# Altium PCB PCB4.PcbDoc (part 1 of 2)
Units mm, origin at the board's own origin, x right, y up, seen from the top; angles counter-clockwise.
Board outline 70 x 70 mm, 2 copper layers (Top Layer, Bottom Layer); 41 components, 63 nets, 218 pads, 36 vias.
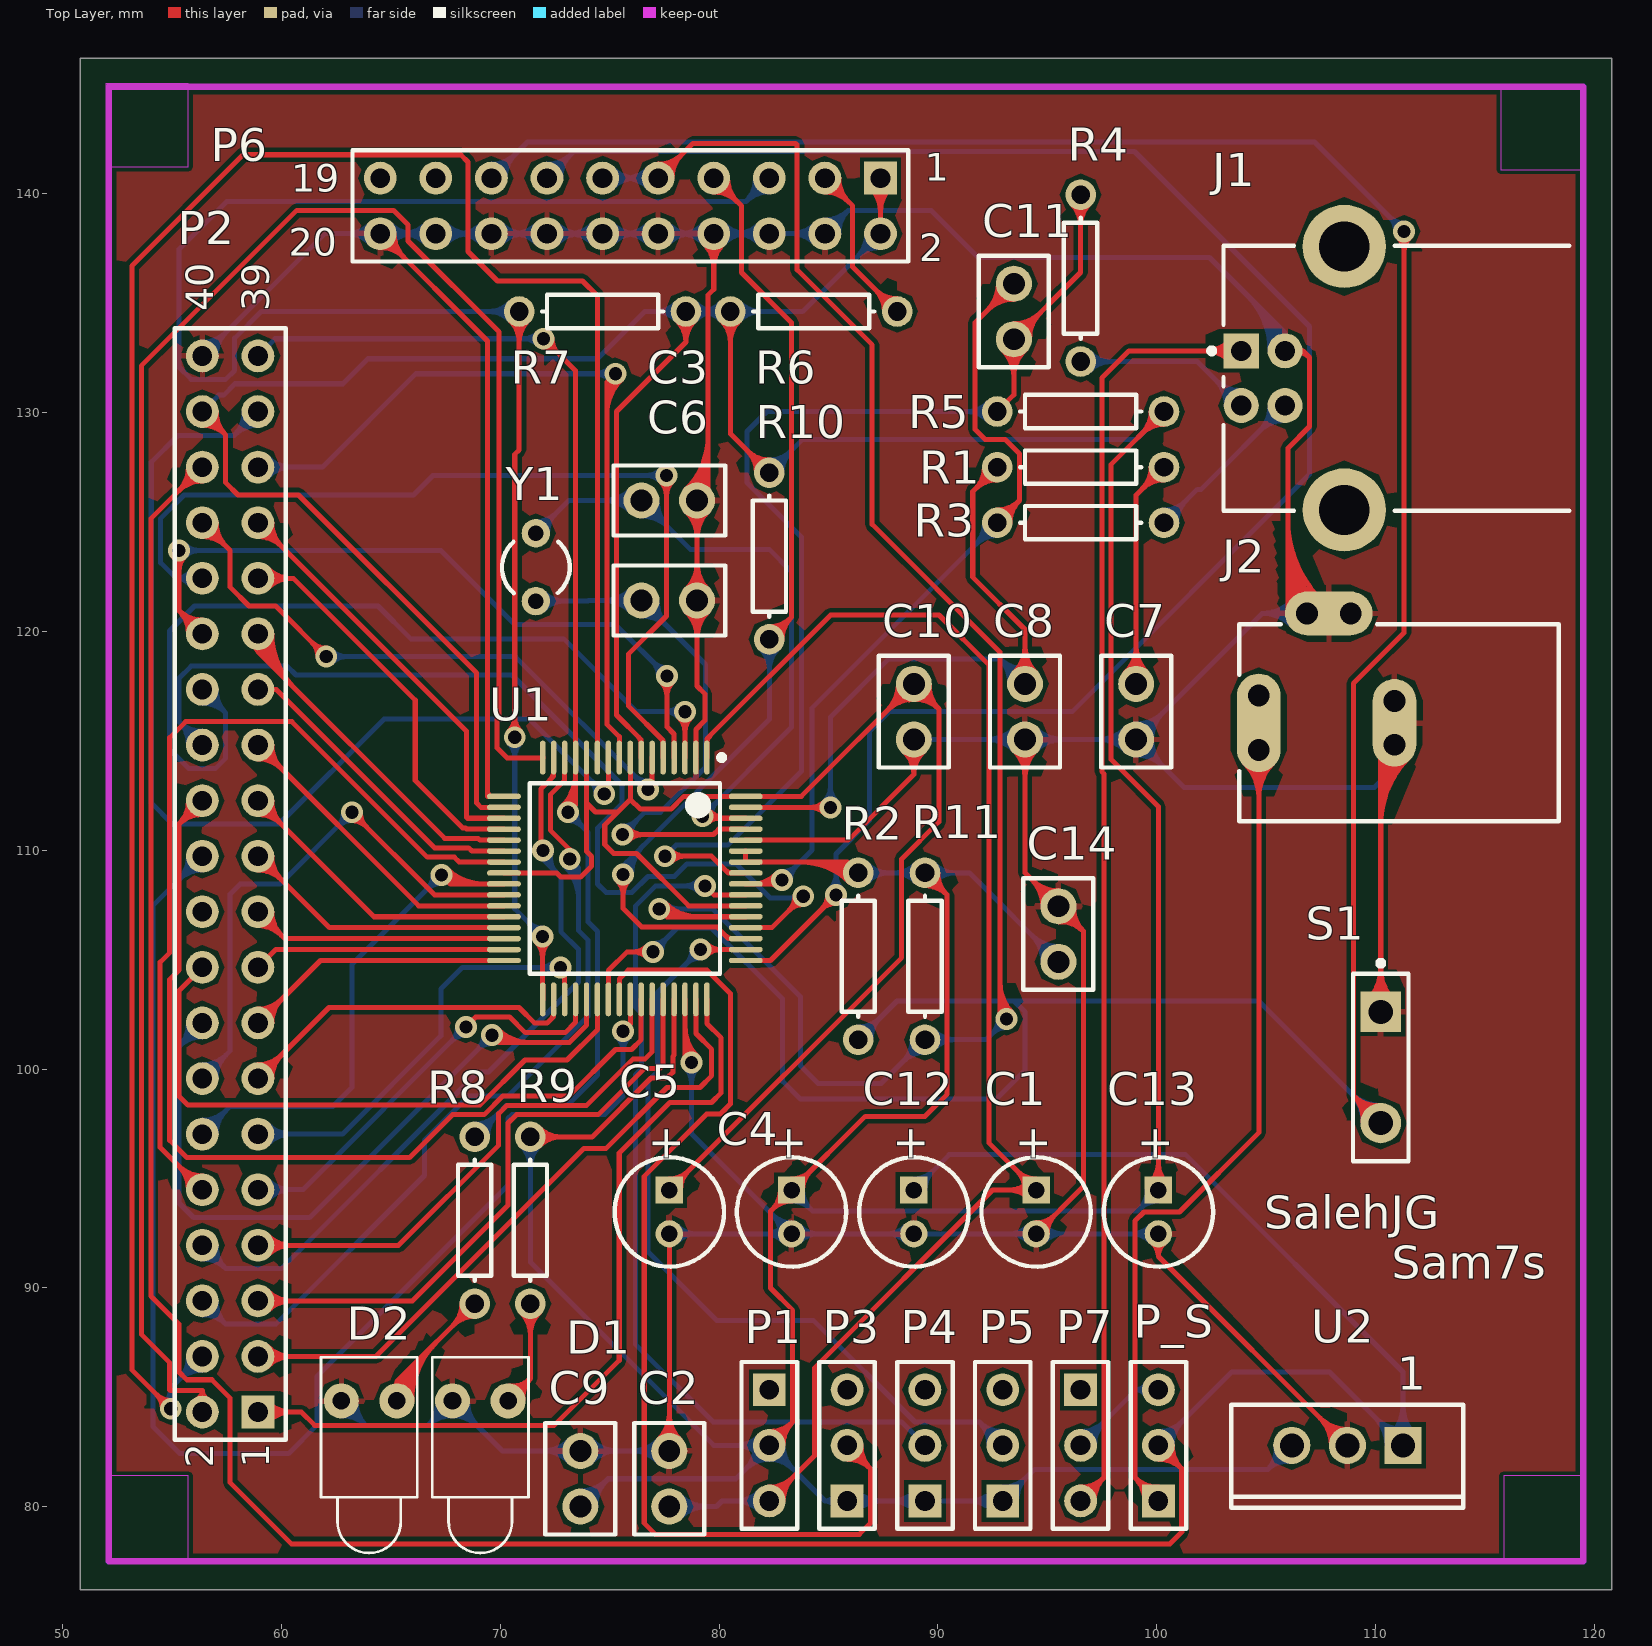
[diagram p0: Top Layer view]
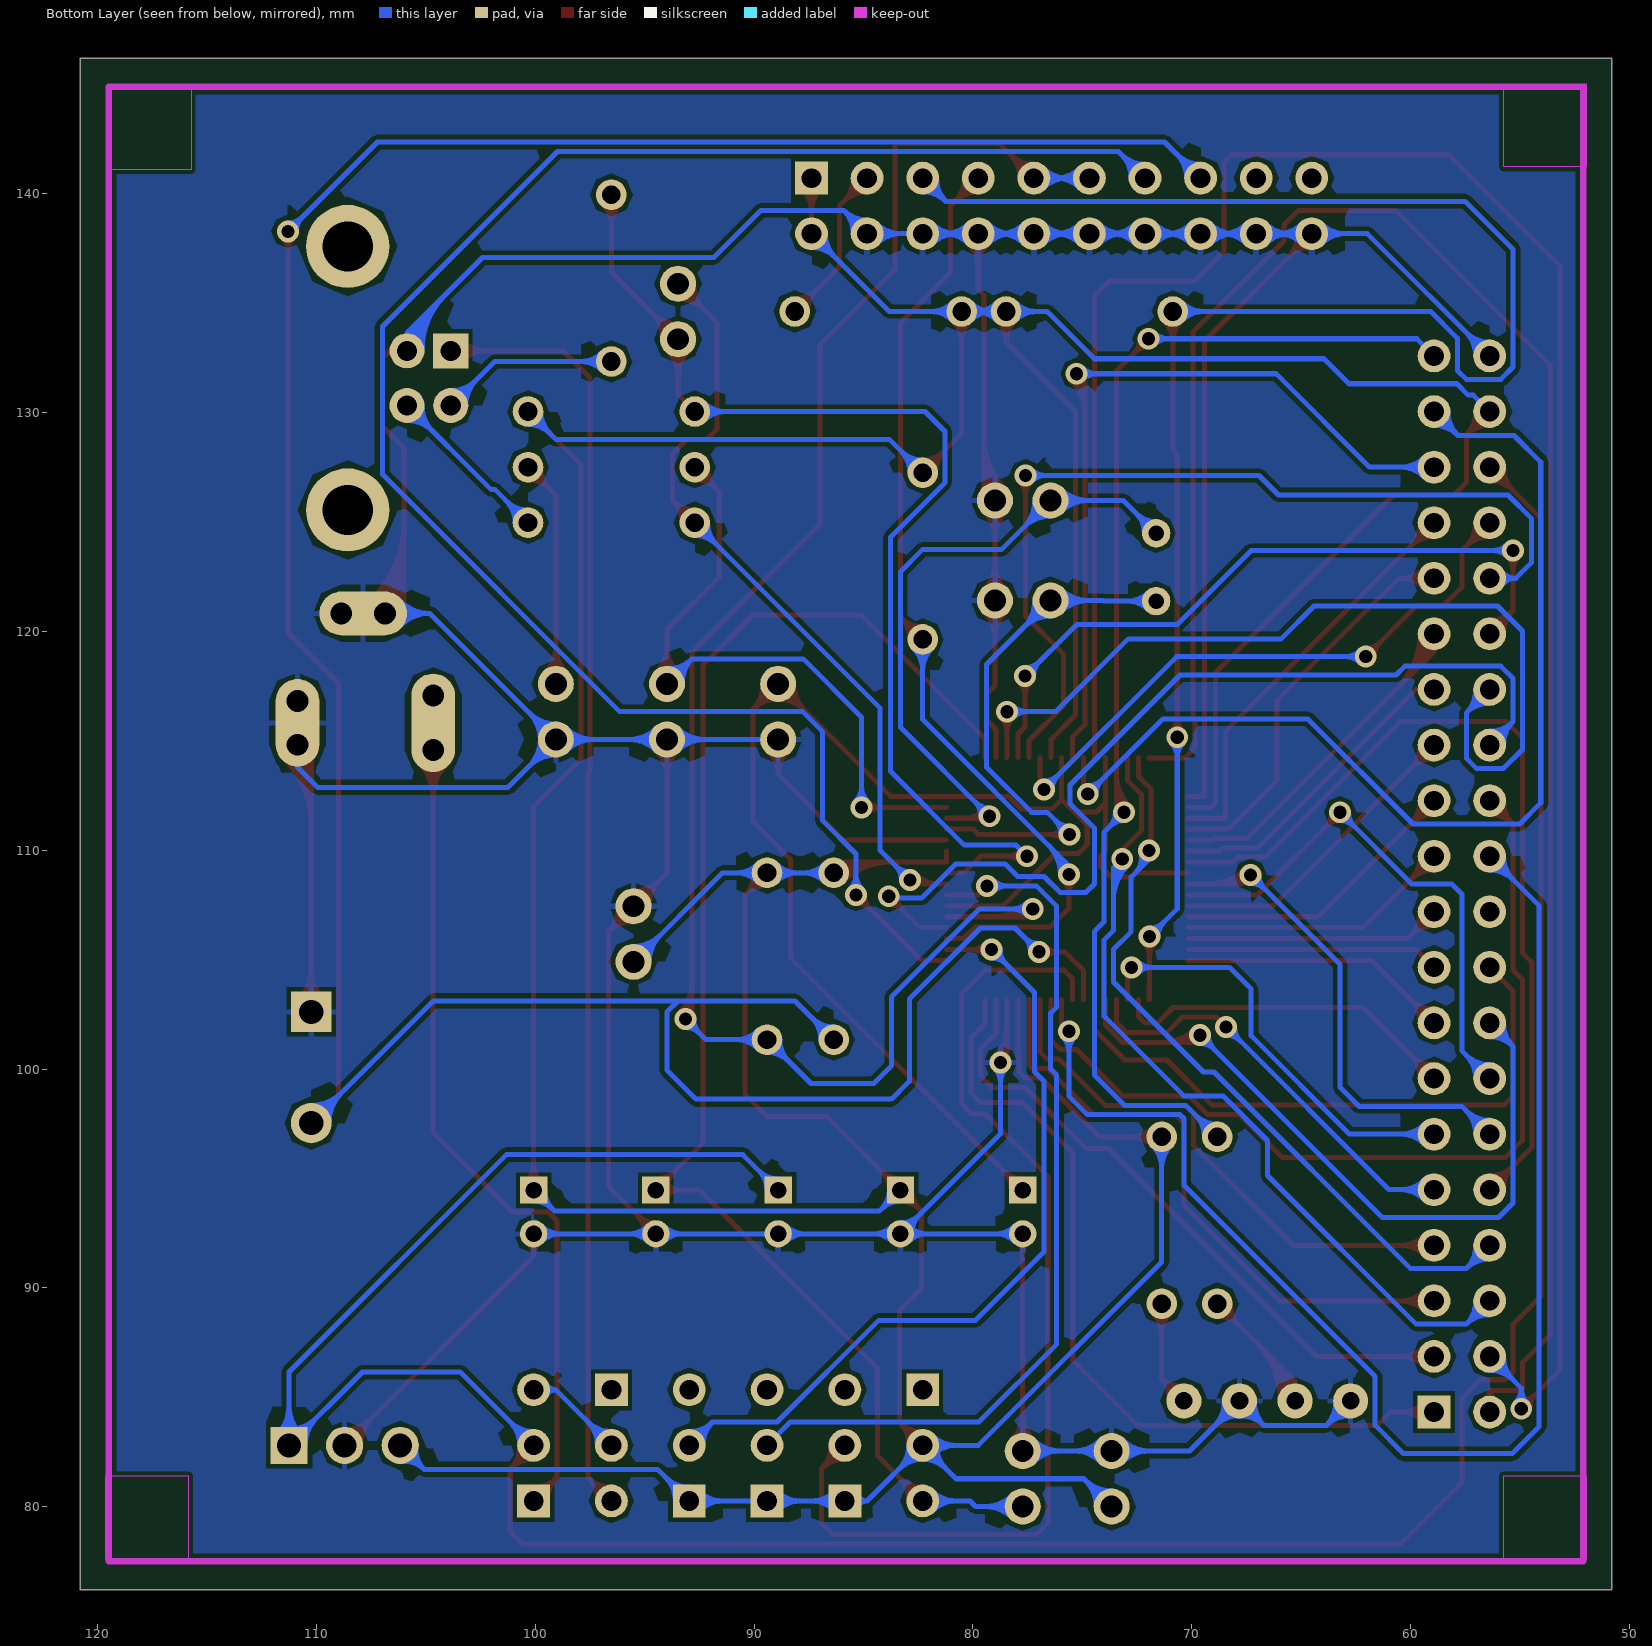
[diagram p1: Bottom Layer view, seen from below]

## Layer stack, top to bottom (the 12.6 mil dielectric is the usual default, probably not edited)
Top Layer: signal copper 0.0356
Dielectric: dielectric 0.32, FR-4, Dk 4.8
Bottom Layer: signal copper 0.0356

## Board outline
50.8,76.2 120.8,76.2 120.8,146.2 50.8,146.2

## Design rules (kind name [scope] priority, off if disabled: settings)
Clearance [All] p1: gap=0.2
PolygonConnect [All] p1: connectstyle=Relief reliefconductorwidth=0.254 reliefentries=4 polygonreliefangle="90 Angle"
RoutingVias [All] p1: holewidth=0.6 width=1 viastyle="Through Hole" minholewidth=0.711 minwidth=1.27 maxholewidth=0.711 maxwidth=1.27
SMDNeckDown [All] p1: percent=100.000
SilkscreenOverComponentPads [All] p1: minsilkscreentomaskgap=0.254
SolderMaskExpansion [All] p1: expansion=0.102
TestPointUsage [All] p1: valid=0 allowmultiple=FALSE
Testpoint [All] p1: side=15 testpointundercomponent=TRUE minsize=1.016 maxsize=2.54 preferedsize=1.524 minholesize=0 maxholesize=1.016 preferedholesize=0.813 testpointgrid=0.025 style=1023 order=0123456789
Width [All] p1: maxlimit=0.3 minlimit=0.2 preferedwidth=0.23
23 further rules are at their usual default settings.

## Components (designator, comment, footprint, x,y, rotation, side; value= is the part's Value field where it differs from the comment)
C1 "Cap Pol1" B 94.488,93.472 r270 top
C2 "Cap" VP32-3.2 77.724,81.28 r270 top
C3 "Cap" VP32-3.2 77.724,125.984 r0 top
C4 "Cap Pol1" B 83.312,93.472 r270 top
C5 "Cap Pol1" B 77.724,93.472 r270 top
C6 "Cap" VP32-3.2 77.724,121.412 r0 top
C7 "Cap" VP32-3.2 99.06,116.332 r270 top
C8 "Cap" VP32-3.2 93.98,116.332 r270 top
C9 "Cap" VP32-3.2 73.66,81.28 r270 top
C10 "Cap" VP32-3.2 88.9,116.332 r90 top
C11 "Cap" VP32-3.2 93.472,134.62 r90 top
C12 "Cap Pol1" B 88.9,93.472 r270 top
C13 "Cap Pol1" B 100.076,93.472 r270 top
C14 "Cap" VP32-3.2 95.504,106.172 r270 top
D1 "LED1" LED-1 69.088,84.836 r270 top
D2 "LED1" LED-1 64.008,84.836 r270 top
J1 "1470156-1" 1470156 118.872,131.572 r0 top
J2 "PWR2.5" KLD-0202 118.364,115.824 r180 top
P1 "Header 3" HDR1X3 82.296,85.344 r270 top
P2 "Header 20X2" HDR2X20 58.928,84.328 r90 top
P3 "Header 3" HDR1X3 85.852,80.264 r90 top
P4 "Header 3" HDR1X3 89.408,80.264 r90 top
P5 "Header 3" HDR1X3 92.964,80.264 r90 top
P6 "Header 10X2" HDR2X10 87.376,140.716 r180 top
P7 "Header 3" HDR1X3 96.52,85.344 r270 top
P_S "Header 3" HDR1X3 100.076,80.264 r90 top (schematic designator Power_Select)
R1 "Res1" AXIAL-0.3 96.52,127.508 r0 top
R2 "Res1" AXIAL-0.3 86.36,105.156 r90 top
R3 "Res1" AXIAL-0.3 96.52,124.968 r180 top
R4 "Res1" AXIAL-0.3 96.52,136.144 r90 top
R5 "Res1" AXIAL-0.3 96.52,130.048 r180 top
R6 "Res1" AXIAL-0.3 84.328,134.62 r0 top
R7 "Res1" AXIAL-0.3 74.676,134.62 r180 top
R8 "Res1" AXIAL-0.3 68.834,93.091 r90 top
R9 "Res1" AXIAL-0.3 71.374,93.091 r270 top
R10 "Res1" AXIAL-0.3 82.296,123.444 r270 top
R11 "Res1" AXIAL-0.3 89.408,105.156 r270 top
S1 "SW-PB" SPST-2 110.236,100.076 r270 top
U1 "AT91SAM7S256-AU-001" LQFP64_L 75.692,108.712 r270 top
U2 "LF33ACV" TO-220A 108.712,82.804 r180 top
Y1 "XTAL" R38 71.628,122.936 r0 top

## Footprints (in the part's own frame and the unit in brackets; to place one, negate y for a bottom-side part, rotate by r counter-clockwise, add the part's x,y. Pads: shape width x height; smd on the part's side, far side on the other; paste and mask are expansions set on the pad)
1470156 [mm] "Connector; USB1.1, Type B, Thru-Hole; 4 Position; Right Angle"
  rect 1.6x1.6 hole 0.92: 1(-15.01,1.25)
  round 1.6 hole 0.92: 2(-15.01,-1.25) 3(-13.01,-1.25) 4(-13.01,1.25)
  round 3.8 hole 2.3: 5(-10.3,6.02) 6(-10.3,-6.02)
  silkscreen extent -16.48,-6.05 -0.02,6.05
AXIAL-0.3 [mm] "Resistor; 2 Leads"
  round 1.4 hole 0.85: 1(-3.81,0) 2(3.81,0)
  silkscreen extent -2.77,-0.76 2.77,0.76
B [mm] "Capacitor, Electrolytic, Radial; Body 5 x 6.8 mm (Dia.xH typ); Pin Spacing 2 mm (typ)"
  rect 1.25x1.25 hole 0.75: 1(-1,0)
  round 1.25 hole 0.75: 2(1,0)
  silkscreen extent -2.5,-2.5 2.5,2.5
HDR1X3 [mm] "Connector; Header; 3 Position"
  rect 1.5x1.5 hole 0.9: 1(0,0)
  round 1.5 hole 0.9: 2(2.54,0) 3(5.08,0)
  silkscreen extent -1.27,-1.27 6.35,1.27
HDR2X10 [mm] "Connector; Header; 10x2 Position"
  rect 1.5x1.5 hole 0.9: 1(0,0)
  round 1.5 hole 0.9: 2(0,2.54) 3(2.54,0) 4(2.54,2.54) 5(5.08,0) 6(5.08,2.54) 7(7.62,0) 8(7.62,2.54) 9(10.16,0) 10(10.16,2.54) 11(12.7,0) 12(12.7,2.54) 13(15.24,0) 14(15.24,2.54) 15(17.78,0) 16(17.78,2.54) 17(20.32,0) 18(20.32,2.54) 19(22.86,0) 20(22.86,2.54)
  silkscreen extent -1.27,-1.27 24.13,3.81
HDR2X20 [mm] "Connector; Header; 20x2 Position"
  rect 1.5x1.5 hole 0.9: 1(0,0)
  round 1.5 hole 0.9: 2(0,2.54) 3(2.54,0) 4(2.54,2.54) 5(5.08,0) 6(5.08,2.54) 7(7.62,0) 8(7.62,2.54) 9(10.16,0) 10(10.16,2.54) 11(12.7,0) 12(12.7,2.54) 13(15.24,0) 14(15.24,2.54) 15(17.78,0) 16(17.78,2.54) 17(20.32,0) 18(20.32,2.54) 19(22.86,0) 20(22.86,2.54) 21(25.4,0) 22(25.4,2.54) 23(27.94,0) 24(27.94,2.54) 25(30.48,0) 26(30.48,2.54) 27(33.02,0) 28(33.02,2.54) 29(35.56,0) 30(35.56,2.54) 31(38.1,0) 32(38.1,2.54) 33(40.64,0) 34(40.64,2.54) 35(43.18,0) 36(43.18,2.54) 37(45.72,0) 38(45.72,2.54) 39(48.26,0) 40(48.26,2.54)
  silkscreen extent -1.27,-1.27 49.53,3.81
KLD-0202 [mm] "DC Power Jack, 2.5mm, KLD Series, PCB Mount"
  oval 2x4.5 all layers, no hole: 1(13.7,0)
  round 1.5 hole 1: 1A(13.7,-1.25) 1B(13.7,1.25) 2A(7.5,-1) 2B(7.5,1) 3A(9.5,-5) 3B(11.5,-5)
  oval 2x4 all layers, no hole: 2(7.5,0)
  oval 4x2 all layers, no hole: 3(10.5,-5)
  silkscreen extent 0,-4.5 14.6,4.5
LED-1 [mm] "Typical RED GaAs LED; 2 Leads"
  round 1.6 hole 0.8: 1(0,1.27) 2(0,-1.27)
  silkscreen extent -2,-2.2 6.95,2.2
LQFP64_L [mm] "Thin QFP, 64-Leads, Body 10x10mm, Pitch 0.5mm, IPC High Density"
  oval 1.55x0.25 smd: 1(-5.525,3.75) 2(-5.525,3.25) 3(-5.525,2.75) 4(-5.525,2.25) 5(-5.525,1.75) 6(-5.525,1.25) 7(-5.525,0.75) 8(-5.525,0.25) 9(-5.525,-0.25) 10(-5.525,-0.75) 11(-5.525,-1.25) 12(-5.525,-1.75) 13(-5.525,-2.25) 14(-5.525,-2.75) 15(-5.525,-3.25) 16(-5.525,-3.75) 33(5.525,-3.75) 34(5.525,-3.25) 35(5.525,-2.75) 36(5.525,-2.25) 37(5.525,-1.75) 38(5.525,-1.25) 39(5.525,-0.75) 40(5.525,-0.25) 41(5.525,0.25) 42(5.525,0.75) 43(5.525,1.25) 44(5.525,1.75) 45(5.525,2.25) 46(5.525,2.75) 47(5.525,3.25) 48(5.525,3.75)
  oval 0.25x1.55 smd: 17(-3.75,-5.525) 18(-3.25,-5.525) 19(-2.75,-5.525) 20(-2.25,-5.525) 21(-1.75,-5.525) 22(-1.25,-5.525) 23(-0.75,-5.525) 24(-0.25,-5.525) 25(0.25,-5.525) 26(0.75,-5.525) 27(1.25,-5.525) 28(1.75,-5.525) 29(2.25,-5.525) 30(2.75,-5.525) 31(3.25,-5.525) 32(3.75,-5.525) 49(3.75,5.525) 50(3.25,5.525) 51(2.75,5.525) 52(2.25,5.525) 53(1.75,5.525) 54(1.25,5.525) 55(0.75,5.525) 56(0.25,5.525) 57(-0.25,5.525) 58(-0.75,5.525) 59(-1.25,5.525) 60(-1.75,5.525) 61(-2.25,5.525) 62(-2.75,5.525) 63(-3.25,5.525) 64(-3.75,5.525)
  silkscreen extent -5.65,-4.35 4.35,4.55, body extent -5,-5 5,5, height 1.6
R38 [mm] "Crystal, Thru-Hole; 2 Leads; Body 3.1 x 8.2 mm (Dia.xH)"
  round 1.3 hole 0.7: 1(0,1.55) 2(0,-1.55)
  silkscreen extent -1.55,-1.19 1.55,1.17
SPST-2 [mm] "Circuit Breaker; 2 Leads"
  rect 1.85x1.85 hole 1.1: 1(-2.54,0)
  round 1.85 hole 1.1: 2(2.54,0)
  silkscreen extent -4.89,-1.27 4.28,1.27
TO-220A [mm] "TO, Thru-Hole, Vertical, Heatsink Mounted; 3 In-Line Leads; Pitch 2.54 mm"
  rect 1.7x1.7 hole 1.1: 1(-2.54,0)
  round 1.7 hole 1.1: 2(0,0) 3(2.54,0)
  silkscreen extent -5.3,-1.85 5.3,2.85
VP32-3.2 [mm] "Capacitor, Ceramic, Thru-Hole, Dipped Radial; Body 5.1 x 3.2 mm (WxT) Pin Spacing 2.54 mm (typ)"
  round 1.65 hole 1: 1(-1.27,0) 2(1.27,0)
  silkscreen extent -2.55,-1.6 2.55,1.6

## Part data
C1 C4 C5 C12 C13: "Polarized Capacitor (Radial)"
C2 C3 C6 C7 C8 C9 C10 C11 C14: "Capacitor"
D1 D2: "Typical RED GaAs LED"
J1: "USB 1.1, Right Angle, Thru-Hole, B Type, Receptacle, 4 Position, White"
J2: "Low Voltage Power Supply Connector"
P1 P3 P4 P5 P7 P_S: "Header, 3-Pin"
P2: "Header, 20-Pin, Dual row"
P6: "Header, 10-Pin, Dual row"
R1 R2 R3 R4 R5 R6 R7 R8 R9 R10 R11: "Resistor"
S1: "Switch"
U1: "Smart ARM Microcontroller, ARM7TDMI 32-Bit RISC CPU, 256KB Flash and 64KB SRAM, 64-Pin LQFP, Industrial, Pb-Free"
U2: "500mA, Very Low Drop (0.45V) Voltage Regulator with Dump Protection (40V)"
Y1: "Crystal Oscillator"

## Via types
v1: diameter 1, hole 0.6, Top Layer to Bottom Layer, 36 vias

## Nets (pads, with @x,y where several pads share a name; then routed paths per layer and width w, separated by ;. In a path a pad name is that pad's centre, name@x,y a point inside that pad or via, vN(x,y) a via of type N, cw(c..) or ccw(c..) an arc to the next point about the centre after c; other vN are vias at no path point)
3.3V: C4.1 C9.2 C13.1 C14.2 P1.2 P2.38 P3.1 P4.1 P5.1 P6.1 P6.2 R2.2 R5.1 R6.1 R7.1 R9.1 R10.1 R11.1 U1.7 U1.18 U1.45 U1.58 U1.59 U2.3 | length 419.9
  Top Layer w0.23: P2.38@56.388,130.048 57.455,128.981 ; P2.38@56.393,129.643 cw(c56.403,128.703) 57.068,129.368 cw(c57.733,130.033) P2.38@56.793,130.043 ; P2.38@56.395,129.413 cw(c56.412,127.939) 57.455,128.981 ; P2.38@57.023,130.041 ccw(c58.497,130.024) 57.455,128.981 ; U1.18@70.167,111.962 69.115,111.962 68.91,112.166 68.91,118.11 60.782,126.238 58.014,126.238 57.455,126.797 57.455,128.981 ; R9.1@71.374,96.901 74.199,96.901 76.89,99.591 77.622,99.591 77.884,99.853 77.884,100.586 77.942,100.644 U1.45@77.942,103.187 ; R9.1@71.625,96.65 cw(c72.231,96.044) 72.231,96.901 cw(c72.231,97.758) R9.1@71.625,97.152 ; R9.1@71.788,96.487 cw(c72.786,95.489) 72.786,96.901 cw(c72.786,98.313) R9.1@71.788,97.315 ; 76.309,115.184 cw(c76.012,114.887) U1.7@76.432,114.887 ; U1.7@76.442,114.237 76.442,115.051 75.311,116.182 75.311,130.052 78.486,133.227 ; R7.1@78.076,134.202 cw(c77.121,133.227) 78.486,133.227 ; R7.1@78.237,134.366 cw(c77.658,133.775) 78.486,133.775 cw(c79.314,133.775) R7.1@78.735,134.366 ; R7.1@78.486,134.62 78.486,133.227 ; R7.1@78.896,134.202 ccw(c79.851,133.227) 78.486,133.227 ; R6.1@80.104,134.206 cw(c79.106,133.208) 80.518,133.208 cw(c81.93,133.208) R6.1@80.932,134.206 ; R6.1@80.267,134.369 cw(c79.661,133.763) 80.518,133.763 cw(c81.375,133.763) R6.1@80.769,134.369 ; R6.1@80.518,134.62 80.518,129.032 R10.1@82.296,127.254 ; U1.59@81.217,109.962 U1.58@81.217,109.462 85.864,109.462 R2.2@86.36,108.966 ; R10.1@81.711,127.254 ccw(c80.299,127.254) 81.297,128.253 ccw(c82.296,129.251) R10.1@82.296,127.839 ; R10.1@81.941,127.254 ccw(c81.084,127.254) 81.69,127.86 ccw(c82.296,128.466) R10.1@82.296,127.609 ; P1.2@82.296,82.804 83.363,83.871 ; P1.2@82.301,83.209 ccw(c82.311,84.149) 82.976,83.484 ccw(c83.641,82.819) P1.2@82.701,82.809 ; P1.2@82.303,83.439 ccw(c82.32,84.913) 83.363,83.871 ; C4.1@82.802,94.472 cw(c81.571,94.472) 82.441,93.601 cw(c83.312,92.731) C4.1@83.312,93.962 ; P1.2@82.931,82.811 cw(c84.405,82.828) 83.363,83.871 ; C4.1@83.032,94.472 cw(c82.356,94.472) 82.834,93.994 cw(c83.312,93.516) C4.1@83.312,94.192 ; C4.1@83.312,94.752 ccw(c83.312,95.428) 83.79,94.95 ccw(c84.268,94.472) C4.1@83.592,94.472 ; C4.1@83.312,94.982 ccw(c83.312,96.213) 84.183,95.343 ccw(c85.053,94.472) C4.1@83.822,94.472 ; 83.75,109.462 cw(c83.75,106.356) R2.2@85.946,108.552 ; 84.305,109.462 cw(c84.305,106.911) R2.2@86.109,108.715 ; 84.861,109.462 cw(c84.861,107.467) R2.2@86.272,108.878 ; 85.416,109.462 cw(c85.416,108.022) R2.2@86.434,109.04 ; P6.1@86.927,140.267 cw(c85.843,139.183) 87.376,139.183 cw(c88.909,139.183) P6.1@87.825,140.267 ; P6.1@87.09,140.43 cw(c86.398,139.738) 87.376,139.738 cw(c88.354,139.738) P6.1@87.662,140.43 ; P6.2@87.376,138.176 P6.1@87.376,140.716 ; R11.1@89.408,108.381 cw(c89.408,106.969) 90.407,107.967 cw(c91.405,108.966) R11.1@89.993,108.966 ; R11.1@89.408,108.611 cw(c89.408,107.754) 90.014,108.36 cw(c90.62,108.966) R11.1@89.763,108.966 ; R11.1@89.408,108.966 90.424,107.95 90.424,98.857 89.408,97.841 86.681,97.841 C4.1@83.312,94.472 82.347,93.507 82.347,89.992 83.363,88.976 83.363,83.871 ; C13.1@99.715,94.833 ccw(c98.845,95.703) 100.076,95.703 ccw(c101.307,95.703) C13.1@100.437,94.833 ; R5.1@99.745,130.048 cw(c98.333,130.048) 99.331,129.049 cw(c100.33,128.051) R5.1@100.33,129.463 ; C13.1@99.878,94.67 ccw(c99.4,95.148) 100.076,95.148 ccw(c100.752,95.148) C13.1@100.274,94.67 ; R5.1@99.975,130.048 cw(c99.118,130.048) 99.724,129.442 cw(c100.33,128.836) R5.1@100.33,129.693 ; C13.1@100.076,94.472 100.076,111.989 97.92,114.145 97.92,127.638 R5.1@100.33,130.048
  Bottom Layer w0.23: P2.38@56.388,130.048 57.135,130.795 57.361,130.795 57.883,131.318 62.814,131.318 63.957,132.461 74.445,132.461 76.604,134.62 R7.1@78.486,134.62 R6.1@80.518,134.62 83.82,134.62 P6.2@87.376,138.176 ; R9.1@70.96,96.487 cw(c69.962,95.489) 71.374,95.489 cw(c72.786,95.489) R9.1@71.788,96.487 ; R9.1@71.123,96.65 cw(c70.517,96.044) 71.374,96.044 cw(c72.231,96.044) R9.1@71.625,96.65 ; R9.1@71.374,96.901 71.374,91.186 79.756,82.804 P1.2@82.296,82.804 ; C9.2@73.66,80.01 74.93,81.28 80.772,81.28 P1.2@82.296,82.804 ; C9.2@73.66,80.49 ccw(c73.66,81.649) 74.479,80.829 ccw(c75.299,80.01) C9.2@74.14,80.01 ; C9.2@73.66,80.72 ccw(c73.66,82.434) 74.872,81.222 ccw(c76.084,80.01) C9.2@74.37,80.01 ; R7.1@78.072,134.206 ccw(c77.074,133.208) 77.074,134.62 ccw(c77.074,136.032) R7.1@78.072,135.034 ; R7.1@78.235,134.369 ccw(c77.629,133.763) 77.629,134.62 ccw(c77.629,135.477) R7.1@78.235,134.871 ; R7.1@78.737,134.369 cw(c79.343,133.763) 79.343,134.62 cw(c79.343,135.477) R7.1@78.737,134.871 ; R7.1@78.9,134.206 cw(c79.898,133.208) 79.898,134.62 cw(c79.898,136.032) R7.1@78.9,135.034 ; R6.1@80.104,134.206 ccw(c79.106,133.208) 79.106,134.62 ccw(c79.106,136.032) R6.1@80.104,135.034 ; R6.1@80.267,134.369 ccw(c79.661,133.763) 79.661,134.62 ccw(c79.661,135.477) R6.1@80.267,134.871 ; R6.1@80.769,134.369 cw(c81.375,133.763) 81.375,134.62 cw(c81.375,135.477) R6.1@80.769,134.871 ; R6.1@80.932,134.206 cw(c81.93,133.208) 81.93,134.62 cw(c81.93,136.032) R6.1@80.932,135.034 ; P1.2@81.661,82.804 cw(c80.128,82.804) 81.212,81.72 cw(c82.296,80.636) 82.296,82.169 cw(c82.296,80.636) 83.38,81.72 cw(c84.464,82.804) P1.2@82.931,82.804 ; P1.2@81.847,82.355 ccw(c80.763,81.271) 80.763,82.804 ccw(c80.763,84.337) P1.2@81.847,83.253 ; P1.2@81.891,82.804 cw(c80.913,82.804) 81.605,82.113 cw(c82.296,81.421) 82.296,82.399 cw(c82.296,81.421) 82.987,82.113 cw(c83.679,82.804) P1.2@82.701,82.804 ; P1.2@82.01,82.518 ccw(c81.318,81.826) 81.318,82.804 ccw(c81.318,83.782) P1.2@82.01,83.09 ; R10.1@82.296,127.254 83.82,128.778 99.06,128.778 R5.1@100.33,130.048 ; R10.1@82.296,127.609 ccw(c82.296,128.466) 82.902,127.86 ccw(c83.508,127.254) R10.1@82.651,127.254 ; R10.1@82.296,127.839 ccw(c82.296,129.251) 83.295,128.253 ccw(c84.293,127.254) R10.1@82.881,127.254 ; C4.1@83.312,93.962 cw(c83.312,92.731) 84.183,93.601 cw(c85.053,94.472) C4.1@83.822,94.472 ; C4.1@83.312,94.192 cw(c83.312,93.516) 83.79,93.994 cw(c84.268,94.472) C4.1@83.592,94.472 ; C4.1@83.312,94.472 84.261,93.523 99.127,93.523 C13.1@100.076,94.472 ; P3.1@85.281,79.986 ccw(c84.836,79.769) 84.836,80.264 ; P3.1@85.281,80.542 cw(c84.836,80.759) 84.836,80.264 ; P3.1@86.138,79.978 cw(c86.83,79.286) 86.83,80.264 cw(c86.83,81.242) P3.1@86.138,80.55 ; P3.1@86.301,79.815 cw(c87.385,78.731) 87.385,80.264 cw(c87.385,81.797) P3.1@86.301,80.713 ; R2.2@86.36,108.966 R11.1@89.408,108.966 91.44,108.966 C14.2@95.504,104.902 ; R2.2@86.611,108.715 cw(c87.217,108.109) 87.217,108.966 cw(c87.217,109.823) R2.2@86.611,109.217 ; P6.2@86.741,138.176 cw(c85.208,138.176) 86.292,137.092 cw(c87.376,136.008) P6.2@87.376,137.541 ; R2.2@86.774,108.552 cw(c87.772,107.554) 87.772,108.966 cw(c87.772,110.378) R2.2@86.774,109.38 ; P6.2@86.971,138.176 cw(c85.993,138.176) 86.685,137.485 cw(c87.376,136.793) P6.2@87.376,137.771 ; P4.1@88.959,79.815 ccw(c87.875,78.731) 87.875,80.264 ccw(c87.875,81.797) P4.1@88.959,80.713 ; R11.1@88.994,108.552 ccw(c87.996,107.554) 87.996,108.966 ccw(c87.996,110.378) R11.1@88.994,109.38 ; P4.1@89.122,79.978 ccw(c88.43,79.286) 88.43,80.264 ccw(c88.43,81.242) P4.1@89.122,80.55 ; R11.1@89.157,108.715 ccw(c88.551,108.109) 88.551,108.966 ccw(c88.551,109.823) R11.1@89.157,109.217 ; R11.1@89.659,108.715 cw(c90.265,108.109) 90.265,108.966 cw(c90.265,109.823) R11.1@89.659,109.217 ; R11.1@89.822,108.552 cw(c90.82,107.554) 90.82,108.966 cw(c90.82,110.378) R11.1@89.822,109.38 ; P5.1@92.515,79.815 ccw(c91.431,78.731) 91.431,80.264 ccw(c91.431,81.797) P5.1@92.515,80.713 ; P5.1@92.678,79.978 ccw(c91.986,79.286) 91.986,80.264 ccw(c91.986,81.242) P5.1@92.678,80.55 ; P5.1@92.964,80.669 ccw(c92.964,81.647) 93.655,80.955 ccw(c94.347,80.264) P5.1@93.369,80.264 ; P5.1@92.964,80.899 ccw(c92.964,82.432) 94.048,81.348 ccw(c95.132,80.264) P5.1@93.599,80.264 ; C14.2@94.794,104.902 ccw(c93.08,104.902) 94.292,106.114 ccw(c95.504,107.326) C14.2@95.504,105.612 ; C14.2@95.024,104.902 ccw(c93.865,104.902) 94.685,105.721 ccw(c95.504,106.541) C14.2@95.504,105.382 ; C13.1@99.566,94.472 cw(c98.335,94.472) 99.205,93.601 cw(c100.076,92.731) C13.1@100.076,93.962 ; R5.1@99.745,130.048 cw(c98.333,130.048) 99.331,129.049 cw(c100.33,128.051) R5.1@100.33,129.463 ; C13.1@99.796,94.472 cw(c99.12,94.472) 99.598,93.994 cw(c100.076,93.516) C13.1@100.076,94.192 ; R5.1@99.975,130.048 cw(c99.118,130.048) 99.724,129.442 cw(c100.33,128.836) R5.1@100.33,129.693 ; U2.3@105.441,82.728 cw(c104.192,82.6) 105.08,81.712 ; U2.3@105.67,82.752 cw(c104.812,82.664) 105.422,82.054 cw(c106.032,81.444) U2.3@106.12,82.302 ; U2.3@106.096,82.073 ccw(c105.968,80.824) 105.08,81.712 ; U2.3@106.172,82.804 105.08,81.712 ; P1.2@82.296,82.804 84.836,80.264 ; 84.836,80.264 P3.1@85.852,80.264 P4.1@89.408,80.264 P5.1@92.964,80.264 94.412,81.712 105.08,81.712
"+5V USB": C12.1 P2.36 P_S.2 U2.1 | length 167.4
  Top Layer w0.23: P2.36@55.753,127.508 cw(c54.22,127.508) 55.304,126.424 cw(c56.388,125.34) P2.36@56.388,126.873 ; P2.36@55.983,127.508 cw(c55.005,127.508) 55.697,126.817 cw(c56.388,126.125) P2.36@56.388,127.103 ; P2.36@56.388,127.508 54.031,125.151 54.031,89.633 55.323,88.341 55.323,86.157 55.677,85.803 56.82,85.803 57.658,84.965 57.658,81.102 60.452,78.308 100.609,78.308 101.143,78.842 101.143,81.737 ; P_S.2@100.076,82.804 101.143,81.737 ; P_S.2@100.081,82.399 cw(c100.091,81.459) 100.756,82.124 cw(c101.421,82.789) P_S.2@100.481,82.799 ; P_S.2@100.083,82.169 cw(c100.1,80.695) 101.143,81.737 ; P_S.2@100.711,82.797 ccw(c102.185,82.78) 101.143,81.737
  Bottom Layer w0.23: C12.1@88.9,94.472 90.516,96.088 101.321,96.088 111.252,86.157 U2.1@111.252,82.804 107.899,86.157 103.429,86.157 P_S.2@100.076,82.804 ; C12.1@88.9,94.752 ccw(c88.9,95.428) 89.378,94.95 ccw(c89.856,94.472) C12.1@89.18,94.472 ; C12.1@88.9,94.982 ccw(c88.9,96.213) 89.771,95.343 ccw(c90.641,94.472) C12.1@89.41,94.472 ; P_S.2@100.076,83.209 ccw(c100.076,84.187) 100.767,83.495 ccw(c101.459,82.804) P_S.2@100.481,82.804 ; P_S.2@100.076,83.439 ccw(c100.076,84.972) 101.16,83.888 ccw(c102.244,82.804) P_S.2@100.711,82.804 ; U2.1@110.517,82.804 ccw(c108.743,82.804) 109.997,84.059 ccw(c111.252,85.313) U2.1@111.252,83.539 ; U2.1@110.732,83.324 ccw(c109.478,84.578) 111.252,84.578 ccw(c113.026,84.578) U2.1@111.772,83.324 ; U2.1@110.747,82.804 ccw(c109.528,82.804) 110.39,83.666 ccw(c111.252,84.528) U2.1@111.252,83.309 ; U2.1@110.895,83.161 ccw(c110.033,84.023) 111.252,84.023 ccw(c112.471,84.023) U2.1@111.609,83.161
A20: P2.2 U1.16 | length 94.2
  Top Layer w0.23: P2.2@56.13,84.908 ccw(c55.953,85.306) 56.388,85.306 ; P2.2@56.388,84.328 56.388,85.306 ; P2.2@56.646,84.908 cw(c56.823,85.306) 56.388,85.306 ; U1.16@71.942,114.237 71.942,114.224 70.307,114.224 69.848,114.683 69.848,115.976 69.952,116.08 69.952,133.68 65.786,137.846 65.786,138.582 65.126,139.243 60.706,139.243 53.601,132.138 53.601,87.877 54.893,86.585 54.893,85.344 54.931,85.306 56.388,85.306
A21: P2.4 U1.11 | length 112.4
  Top Layer w0.23: v1@54.555,84.48 ccw(c53.626,84.48) 54.283,85.138 ccw(c54.94,85.795) v1@54.94,84.865 ; v1(54.94,84.48) 53.162,86.258 53.162,136.703 58.242,141.783 68.199,141.783 68.529,141.453 68.529,137.363 69.875,136.017 73.762,136.017 74.442,135.337 U1.11@74.442,114.237
  Bottom Layer w0.23: v1@54.668,84.753 ccw(c54.011,85.41) 54.94,85.41 ccw(c55.87,85.41) v1@55.212,84.753 ; v1(54.94,84.48) 54.94,85.42 P2.4@56.388,86.868 ; P2.4@55.753,86.868 cw(c54.22,86.868) 55.304,85.784 cw(c56.388,84.7) P2.4@56.388,86.233 ; P2.4@55.983,86.868 cw(c55.005,86.868) 55.697,86.177 cw(c56.388,85.485) P2.4@56.388,86.463
A22: P2.6 U1.14 | length 45.6
  Top Layer w0.23: U1.14@72.942,114.237 72.942,113.194 72.286,112.538 72.286,110.92 73.177,110.028 v1(73.177,109.601)
  Bottom Layer w0.23: P2.6@56.388,89.408 57.455,88.341 ; P2.6@56.393,89.003 cw(c56.403,88.063) 57.068,88.728 cw(c57.733,89.393) P2.6@56.793,89.403 ; P2.6@56.395,88.773 cw(c56.412,87.299) 57.455,88.341 ; P2.6@57.023,89.401 ccw(c58.497,89.384) 57.455,88.341 ; v1@72.905,109.329 cw(c71.267,107.69) 73.584,107.69 ; v1@73.068,109.491 cw(c71.822,108.246) 73.584,108.246 ; v1(73.177,109.601) 73.584,109.195 73.584,106.325 74.002,105.907 74.002,102.413 70.365,98.776 68.575,98.776 66.537,96.737 66.537,95.137 59.741,88.341 57.455,88.341 ; v1@73.23,109.654 cw(c72.377,108.801) 73.584,108.801
A23: P2.8 U1.15 | length 40.2
  Top Layer w0.23: v1(71.958,109.982) 71.856,110.084 71.856,112.8 72.442,113.386 U1.15@72.442,114.237 ; 72.283,113.226 ccw(c71.922,113.587) U1.15@72.432,113.587
  Bottom Layer w0.23: P2.8@56.388,91.948 57.455,90.881 ; P2.8@56.393,91.543 cw(c56.403,90.603) 57.068,91.268 cw(c57.733,91.933) P2.8@56.793,91.943 ; P2.8@56.395,91.313 cw(c56.412,89.839) 57.455,90.881 ; P2.8@57.023,91.941 ccw(c58.497,91.924) 57.455,90.881 ; v1(71.958,109.982) 71.958,109.583 72.771,108.77 72.771,106.278 73.572,105.477 73.572,103.976 69.465,99.869 68.983,99.869 59.995,90.881 57.455,90.881 ; v1@72.108,109.941 ccw(c72.795,109.754) 72.291,109.25 ; v1@72.33,109.88 ccw(c73.236,109.634) 72.572,108.97
A24: P2.10 U1.23 | length 43.8
  Top Layer w0.23: P2.10@55.753,94.488 ccw(c54.22,94.488) 55.304,95.572 ccw(c56.388,96.656) P2.10@56.388,95.123 ; P2.10@55.983,94.488 ccw(c55.005,94.488) 55.697,95.179 ccw(c56.388,95.871) P2.10@56.388,94.893 ; P2.10@56.388,94.488 54.461,96.415 54.461,104.885 54.893,105.317 54.893,115.142 55.626,115.875 60.478,115.875 66.669,109.683 67.904,109.683 68.125,109.462 U1.23@70.167,109.462
A25: P2.12 U1.25 | length 31.7
  Top Layer w0.23: v1@67.257,108.815 ccw(c68.11,109.668) 68.11,108.462 ; v1(67.31,108.868) 67.716,108.462 U1.25@70.167,108.462 ; v1@67.42,108.978 ccw(c68.665,110.224) 68.665,108.462 ; v1@67.582,109.141 ccw(c69.221,110.779) 69.221,108.462
  Bottom Layer w0.23: P2.12@56.388,97.028 57.658,98.298 62.357,98.298 63.221,99.162 63.221,104.779 v1(67.31,108.868) ; P2.12@56.388,97.433 ccw(c56.388,98.411) 57.079,97.719 ccw(c57.771,97.028) P2.12@56.793,97.028 ; P2.12@56.388,97.663 ccw(c56.388,99.196) 57.472,98.112 ccw(c58.556,97.028) P2.12@57.023,97.028 ; v1@66.925,108.868 cw(c65.996,108.868) 66.653,108.211 cw(c67.31,107.554) v1@67.31,108.483
A26: P2.14 U1.26 | length 31.4
  Top Layer w0.23: v1@63.221,111.35 cw(c63.221,110.42) 63.878,111.077 cw(c64.535,111.735) v1@63.606,111.735 ; v1(63.221,111.735) 66.993,107.962 U1.26@70.167,107.962
  Bottom Layer w0.23: P2.14@56.388,99.568 57.658,100.838 57.658,108.001 58.115,108.458 59.944,108.458 v1(63.221,111.735) ; P2.14@56.388,99.973 ccw(c56.388,100.951) 57.079,100.259 ccw(c57.771,99.568) P2.14@56.793,99.568 ; P2.14@56.388,100.203 ccw(c56.388,101.736) 57.472,100.652 ccw(c58.556,99.568) P2.14@57.023,99.568 ; v1@62.836,111.735 cw(c61.906,111.735) 62.563,111.077 cw(c63.221,110.42) v1@63.221,111.35
A27: P2.16 U1.37 | length 41.5
  Top Layer w0.23: v1@69.568,101.496 ccw(c70.238,102.165) 70.238,101.219 ; v1(69.621,101.549) 69.952,101.219 73.155,101.219 73.942,102.006 U1.37@73.942,103.187 ; v1@69.731,101.659 ccw(c70.793,102.721) 70.793,101.219 ; v1@69.894,101.821 ccw(c71.348,103.276) 71.348,101.219
  Bottom Layer w0.23: P2.16@55.753,102.101 cw(c54.279,102.084) 55.321,101.041 ; P2.16@55.983,102.103 cw(c55.043,102.093) 55.708,101.428 cw(c56.373,100.763) P2.16@56.383,101.703 ; P2.16@56.381,101.473 ccw(c56.364,99.999) 55.321,101.041 ; P2.16@56.388,102.108 55.321,101.041 ; v1@69.236,101.549 cw(c68.307,101.549) 68.964,100.892 cw(c69.621,100.235) v1@69.621,101.164 ; v1(69.621,101.549) 61.29,93.218 55.982,93.218 55.321,93.878 55.321,101.041
A28: P2.18 U1.38 | length 28.4
  Top Layer w0.23: P2.18@56.388,104.648 55.323,103.583 55.323,98.753 55.728,98.349 69.066,98.349 71.134,100.417 73.055,100.417 74.442,101.804 U1.38@74.442,103.187
A29: P2.22 U1.41 | length 68.8
  Top Layer w0.23: v1(75.616,101.727) 75.942,102.053 U1.41@75.942,103.187
  Bottom Layer w0.23: P2.22@55.753,109.728 cw(c54.22,109.728) 55.304,108.644 cw(c56.388,107.56) P2.22@56.388,109.093 ; P2.22@55.983,109.728 cw(c55.005,109.728) 55.697,109.037 cw(c56.388,108.345) P2.22@56.388,109.323 ; P2.22@56.388,109.728 54.125,107.465 54.125,83.665 55.368,82.423 60.325,82.423 61.62,83.718 61.62,85.954 70.358,94.691 70.358,97.739 70.535,97.916 74.778,97.916 75.616,98.754 v1(75.616,101.727) ; v1@75.344,101.455 cw(c74.686,100.798) 75.616,100.798 cw(c76.545,100.798) v1@75.888,101.455
A30: P2.24 U1.42 | length 45.9
  Top Layer w0.23: P2.24@55.753,112.26 cw(c54.285,112.241) 55.323,111.203 ; P2.24@55.983,112.263 cw(c55.046,112.251) 55.709,111.589 cw(c56.371,110.926) P2.24@56.383,111.863 ; P2.24@56.38,111.633 ccw(c56.361,110.165) 55.323,111.203 ; P2.24@56.388,112.268 55.323,111.203 ; U1.42@76.442,103.187 76.442,101.342 75.997,100.897 75.268,100.897 73.147,98.776 70.125,98.776 69.266,97.917 67.818,97.917 65.862,95.961 55.679,95.961 54.892,96.749 54.892,104.09 55.323,104.521 55.323,111.203
A31: P2.26 U1.52 | length 50.5
  Top Layer w0.23: U1.52@81.217,106.462 82.408,106.462 v1(83.845,107.899) ; v1@83.46,107.899 cw(c82.531,107.899) 83.188,107.242 cw(c83.845,106.585) v1@83.845,107.514
  Bottom Layer w0.23: P2.26@55.753,114.815 ccw(c54.279,114.832) 55.321,115.875 ; P2.26@55.983,114.813 ccw(c55.043,114.823) 55.708,115.488 ccw(c56.373,116.153) P2.26@56.383,115.213 ; P2.26@56.381,115.443 cw(c56.364,116.917) 55.321,115.875 ; P2.26@56.388,114.808 55.321,115.875 ; v1(83.845,107.899) 83.767,107.821 82.332,107.821 80.774,109.379 78.532,109.379 77.955,108.802 76.752,108.802 76.024,108.075 74.828,108.075 74.444,108.459 74.444,111.007 75.567,112.13 75.567,112.979 70.533,118.013 60.666,118.013 60.264,118.415 55.88,118.415 55.321,117.856 55.321,115.875
AD4: P2.28 U1.3 | length 47
  Top Layer w0.23: v1@78.17,116.06 cw(c77.513,115.403) 78.442,115.403 cw(c79.371,115.403) v1@78.714,116.06 ; U1.3@78.442,114.237 v1(78.442,116.332)
  Bottom Layer w0.23: P2.28@56.388,117.348 57.455,116.281 ; P2.28@56.393,116.943 cw(c56.403,116.003) 57.068,116.668 cw(c57.733,117.333) P2.28@56.793,117.343 ; P2.28@56.395,116.713 cw(c56.412,115.239) 57.455,116.281 ; P2.28@57.023,117.341 ccw(c58.497,117.324) 57.455,116.281 ; v1@78.17,116.06 ccw(c77.513,115.403) 77.513,116.332 ccw(c77.513,117.261) v1@78.17,116.604 ; v1(78.442,116.332) 76.225,116.332 72.898,119.659 65.913,119.659 64.414,121.158 56.032,121.158 54.889,120.015 54.889,114.605 55.753,113.741 56.998,113.741 57.455,114.198 57.455,116.281
AD5: P2.30 U1.4 | length 42.5
  Top Layer w0.23: v1@55.049,123.426 cw(c54.392,122.769) 55.321,122.769 cw(c56.251,122.769) v1@55.593,123.426 ; v1(55.321,123.698) 55.321,120.955 ; P2.30@55.753,119.895 ccw(c54.279,119.912) 55.321,120.955 ; P2.30@55.983,119.893 ccw(c55.043,119.903) 55.708,120.568 ccw(c56.373,121.233) P2.30@56.383,120.293 ; P2.30@56.381,120.523 cw(c56.364,121.997) 55.321,120.955 ; P2.30@56.388,119.888 55.321,120.955 ; v1@77.343,117.692 cw(c76.686,117.035) 77.616,117.035 cw(c78.545,117.035) v1@77.888,117.692 ; v1(77.616,117.964) 77.616,115.642 77.942,115.316 U1.4@77.942,114.237
  Bottom Layer w0.23: v1(55.321,123.698) 67.285,123.698 70.663,120.32 75.26,120.32 v1(77.616,117.964) ; v1@55.593,123.426 cw(c56.251,122.769) 56.251,123.698 cw(c56.251,124.627) v1@55.593,123.97 ; v1@77.231,117.964 ccw(c76.301,117.964) 76.958,118.622 ccw(c77.616,119.279) v1@77.616,118.349
AD6: P2.32 U1.5 | length 48.2
  Top Layer w0.23: v1@77.325,126.855 cw(c76.668,126.198) 77.597,126.198 cw(c78.526,126.198) v1@77.869,126.855 ; 77.337,115.116 cw(c77.108,114.887) U1.5@77.432,114.887 ; U1.5@77.442,114.237 77.442,115.011 75.87,116.583 75.87,118.974 77.597,120.701 v1(77.597,127.127)
  Bottom Layer w0.23: P2.32@55.861,122.073 ccw(c55.194,121.623) 55.194,122.428 ; P2.32@55.861,122.783 cw(c55.194,123.233) 55.194,122.428 ; P2.32@56.052,122.202 ccw(c55.627,121.915) 55.627,122.428 ccw(c55.627,122.941) P2.32@56.052,122.654 ; P2.32@56.388,122.428 55.194,122.428 ; v1@77.325,126.855 ccw(c76.668,126.198) 76.668,127.127 ccw(c76.668,128.056) v1@77.325,127.399 ; v1(77.597,127.127) 66.929,127.127 66.04,126.238 55.55,126.238 54.483,125.171 54.483,123.139 55.194,122.428
AD7: P2.34 U1.6 | length 36.3
  Top Layer w0.23: P2.34@56.388,124.333 cw(c56.388,122.8) 57.472,123.884 cw(c58.556,124.968) P2.34@57.023,124.968 ; P2.34@56.388,124.563 cw(c56.388,123.585) 57.079,124.277 cw(c57.771,124.968) P2.34@56.793,124.968 ; P2.34@56.388,124.968 57.658,123.698 57.658,122.022 58.522,121.158 59.739,121.158 v1(62.05,118.847) ; v1@61.665,118.847 ccw(c60.736,118.847) 61.393,119.504 ccw(c62.05,120.161) v1@62.05,119.232 ; v1(76.759,112.776) 76.942,112.959 U1.6@76.942,114.237
  Bottom Layer w0.23: v1(62.05,118.847) 70.688,118.847 v1(76.759,112.776) ; v1@62.323,118.574 cw(c62.98,117.917) 62.98,118.847 cw(c62.98,119.776) v1@62.323,119.119 ; v1@76.374,112.776 ccw(c75.444,112.776) 76.102,113.433 ccw(c76.759,114.09) v1@76.759,113.161
ADVREF: C1.1 C2.2 P1.3 U1.1 | length 85.8
  Top Layer w0.23: U1.1@79.442,114.237 79.442,115.094 85.099,120.752 90.052,120.752 92.327,118.477 92.327,96.633 C1.1@94.488,94.472 92.491,94.472 84.353,86.335 84.353,82.321 P1.3@82.296,80.264 ; U1.1@79.452,114.887 cw(c79.977,114.887) 79.606,115.258 ; P1.3@82.296,80.669 ccw(c82.296,81.647) 82.987,80.955 ccw(c83.679,80.264) P1.3@82.701,80.264 ; P1.3@82.296,80.899 ccw(c82.296,82.432) 83.38,81.348 ccw(c84.464,80.264) P1.3@82.931,80.264 ; C1.1@93.978,94.472 ccw(c92.747,94.472) 93.617,95.343 ccw(c94.488,96.213) C1.1@94.488,94.982 ; C1.1@94.127,94.111 ccw(c93.257,93.241) 93.257,94.472 ccw(c93.257,95.703) C1.1@94.127,94.833 ; C1.1@94.208,94.472 ccw(c93.532,94.472) 94.01,94.95 ccw(c94.488,95.428) C1.1@94.488,94.752 ; C1.1@94.29,94.274 ccw(c93.812,93.796) 93.812,94.472 ccw(c93.812,95.148) C1.1@94.29,94.67
  Bottom Layer w0.23: C2.2@77.724,80.01 79.883,80.01 80.137,80.264 P1.3@82.296,80.264 ; C2.2@78.063,79.671 cw(c78.883,78.851) 78.883,80.01 cw(c78.883,81.169) C2.2@78.063,80.349 ; C2.2@78.226,79.508 cw(c79.438,78.296) 79.438,80.01 cw(c79.438,81.724) C2.2@78.226,80.512 ; P1.3@81.847,79.815 ccw(c80.763,78.731) 80.763,80.264 ccw(c80.763,81.797) P1.3@81.847,80.713 ; P1.3@82.01,79.978 ccw(c81.318,79.286) 81.318,80.264 ccw(c81.318,81.242) P1.3@82.01,80.55
DDM: C11.2 R3.2 U1.56 | length 50.9
  Top Layer w0.23: U1.56@81.217,108.462 82.706,108.462 v1(82.88,108.636) ; U1.56@81.531,108.462 ccw(c81.531,109.985) v1@82.608,108.908 ; 82.086,108.462 ccw(c82.086,109.43) v1@82.771,108.745 ; 82.37,108.462 cw(c82.37,108.126) v1@82.608,108.364 ; R3.2@92.71,124.968 93.726,125.984 93.726,128.118 93.066,128.778 92.151,128.778 91.694,129.235 91.694,134.112 C11.2@93.472,135.89 ; R3.2@92.71,125.323 ccw(c92.71,126.18) 93.316,125.574 ccw(c93.922,124.968) R3.2@93.065,124.968 ; R3.2@92.71,125.553 ccw(c92.71,126.965) 93.709,125.967 ccw(c94.707,124.968) R3.2@93.295,124.968 ; C11.2@92.762,135.89 cw(c91.048,135.89) 92.26,134.678 cw(c93.472,133.466) C11.2@93.472,135.18 ; C11.2@92.992,135.89 cw(c91.833,135.89) 92.653,135.071 cw(c93.472,134.251) C11.2@93.472,135.41
  Bottom Layer w0.23: v1(82.88,108.636) 84.252,110.007 84.252,116.51 R3.2@92.71,124.968 ; v1@82.88,109.021 ccw(c82.88,109.95) 83.537,109.293 ccw(c84.195,108.636) v1@83.265,108.636 ; R3.2@92.125,124.968 cw(c90.713,124.968) 91.711,123.969 cw(c92.71,122.971) R3.2@92.71,124.383 ; R3.2@92.355,124.968 cw(c91.498,124.968) 92.104,124.362 cw(c92.71,123.756) R3.2@92.71,124.613
DDP: C11.1 R4.2 R5.2 U1.57 | length 69.6
  Top Layer w0.23: v1(77.521,109.728) 79.654,109.728 80.42,108.962 U1.57@81.217,108.962 ; v1@77.793,109.456 cw(c78.45,108.799) 78.45,109.728 cw(c78.45,110.657) v1@77.793,110 ; 80.3,109.083 ccw(c80.567,109.35) U1.57@80.567,108.972 ; R5.2@92.71,130.048 93.472,130.81 C11.1@93.472,133.35 96.52,136.398 R4.2@96.52,139.954 ; C11.1@92.97,132.848 cw(c91.758,131.636) 93.472,131.636 cw(c95.186,131.636) C11.1@93.974,132.848 ; C11.1@93.133,133.011 cw(c92.313,132.191) 93.472,132.191 cw(c94.631,132.191) C11.1@93.811,133.011 ; C11.1@93.472,133.83 ccw(c93.472,134.989) 94.291,134.169 ccw(c95.111,133.35) C11.1@93.952,133.35 ; C11.1@93.472,134.06 ccw(c93.472,135.774) 94.684,134.562 ccw(c95.896,133.35) C11.1@94.182,133.35 ; R4.2@96.106,139.54 cw(c95.108,138.542) 96.52,138.542 cw(c97.932,138.542) R4.2@96.934,139.54 ; R4.2@96.269,139.703 cw(c95.663,139.097) 96.52,139.097 cw(c97.377,139.097) R4.2@96.771,139.703
  Bottom Layer w0.23: v1(77.521,109.728) 78.028,110.236 80.391,110.236 83.769,113.614 83.769,124.308 81.28,126.797 81.28,129.134 82.194,130.048 R5.2@92.71,130.048 ; R5.2@92.296,129.634 ccw(c91.298,128.636) 91.298,130.048 ccw(c91.298,131.46) R5.2@92.296,130.462 ; R5.2@92.459,129.797 ccw(c91.853,129.191) 91.853,130.048 ccw(c91.853,130.905) R5.2@92.459,130.299
ERASE: P4.2 U1.55 | length 42.5
  Top Layer w0.23: v1(79.35,108.372) 79.76,107.962 U1.55@81.217,107.962
  Bottom Layer w0.23: v1@79.077,108.1 ccw(c78.42,107.443) 78.42,108.372 ccw(c78.42,109.302) v1@79.077,108.644 ; v1(79.35,108.372) 77.102,108.372 76.172,107.442 76.172,102.829 76.447,102.555 76.447,100.002 76.172,99.728 76.172,87.429 79.731,83.871 88.341,83.871 P4.2@89.408,82.804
